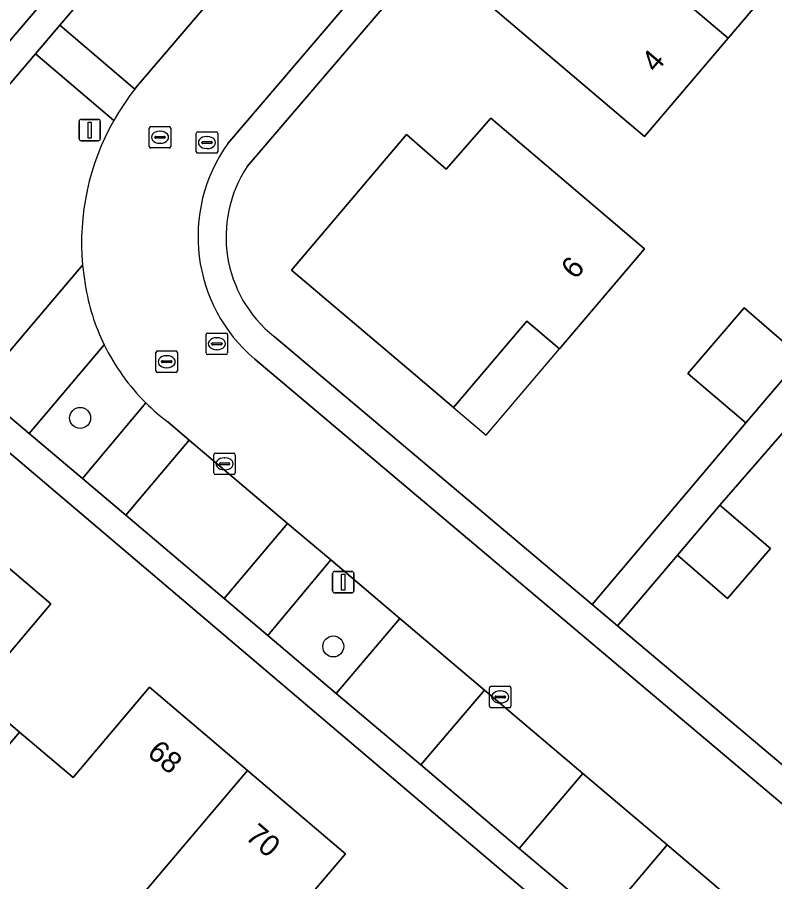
# Model space of a CAD drawing. Extents: x 156412 to 157779, y 382335 to 383768.
# Drawn here: x 156801.54 to 156836.83, y 382429.31 to 382469.61 of the extents above; entities that cross this region are included whole.
import ezdxf

# ---------------------------------------------------------------- set-up
doc = ezdxf.new("R2010")
doc.units = 0
for name, color, linetype in [('IMGEO_Berm_groen', 7, 'Continuous'), ('IMGEO_Boom', 7, 'Continuous'), ('IMGEO_Erf', 7, 'Continuous'), ('IMGEO_Groenvoorziening', 7, 'Continuous'), ('IMGEO_Kolk', 7, 'Continuous'), ('IMGEO_Lichtmast', 7, 'Continuous'), ('IMGEO_Pand', 7, 'Continuous'), ('IMGEO_Pand_nummerreeks', 7, 'Continuous'), ('IMGEO_Pand_overbouw', 7, 'Continuous'), ('IMGEO_Parkeervlak_open', 7, 'Continuous'), ('IMGEO_Rijbaan_lokaal_open', 7, 'Continuous'), ('IMGEO_Rioolput', 7, 'Continuous'), ('IMGEO_Voetpad_open', 7, 'Continuous')]:
    doc.layers.add(name, color=color, linetype=linetype)

msp = doc.modelspace()

# ---------------------------------------------------------------- linework, layer by layer
at = {"layer": 'IMGEO_Berm_groen'}
for points in [[(156806.038, 382464.795), (156802.386, 382467.905), (156794.793, 382458.992)], [(156795.115, 382456.117), (156799.666, 382452.263), (156804.586, 382458.056)], [(156805.592, 382454.345), (156802.099, 382450.202), (156804.578, 382448.103), (156807.536, 382451.631)]]:
    msp.add_lwpolyline(points, dxfattribs=at)
for points in [[(156819.362, 382441.59), (156816.15, 382444.311), (156813.213, 382440.791), (156816.404, 382438.089)], [(156835.024, 382428.321), (156831.828, 382431.028), (156828.869, 382427.532), (156832.065, 382424.824)]]:
    msp.add_lwpolyline(points, close=True, dxfattribs=at)
for centre, radius, start, end in [((156816.088, 382459.104), 11.549, 150.4766, 185.205), ((156814.578, 382458.729), 9.998, 206.0032, 225.2238)]:
    msp.add_arc(centre, radius, start, end, dxfattribs=at)
at = {"layer": 'IMGEO_Boom'}
for centre in [(156804.472, 382450.932), (156816.266, 382440.281)]:
    msp.add_circle(centre, 0.489, dxfattribs=at)
at = {"layer": 'IMGEO_Erf'}
for points in [[(156877.342, 382453.394), (156835.001, 382489.257), (156812.259, 382462.651)], [(156813.512, 382454.727), (156828.335, 382442.229), (156835.48, 382450.702), (156832.784, 382453.003), (156835.405, 382456.06), (156838.087, 382453.751), (156844.039, 382460.712), (156843.159, 382461.477), (156846.108, 382464.976), (156848.523, 382462.877), (156845.52, 382459.424), (156844.272, 382457.989), (156844.07, 382458.164), (156843.904, 382457.972), (156840.037, 382453.506), (156842.315, 382451.578), (156839.698, 382448.487), (156837.386, 382450.444), (156834.276, 382446.87), (156836.632, 382444.85), (156834.638, 382442.513), (156832.298, 382444.54), (156829.512, 382441.236), (156849.402, 382424.466)], [(156849.783, 382408.111), (156821.763, 382431.828), (156791.675, 382457.364), (156791.237, 382457.729), (156772.208, 382435.618), (156781.23, 382428.836)], [(156799.87, 382429.132), (156797.367, 382431.255), (156798.968, 382433.123), (156796.887, 382434.907), (156796.85, 382434.939), (156796.239, 382434.225), (156791.957, 382437.897), (156790.909, 382436.674), (156790.691, 382436.861), (156788.408, 382438.819), (156783.803, 382442.767), (156791.692, 382451.968), (156796.235, 382448.073), (156792.687, 382443.876), (156794.997, 382441.95), (156798.545, 382446.146), (156803.106, 382442.264), (156799.551, 382438.056), (156801.645, 382436.286), (156804.14, 382434.178), (156807.696, 382438.387), (156812.265, 382434.503), (156816.834, 382430.618), (156813.267, 382426.411)]]:
    msp.add_lwpolyline(points, dxfattribs=at)
for points in [[(156838.619, 382472.532), (156838.242, 382472.852), (156834.658, 382468.629), (156830.77, 382464.048), (156829.953, 382464.737), (156822.38, 382471.184), (156826.257, 382475.755), (156830.134, 382480.326), (156833.182, 382477.737), (156835.544, 382480.522), (156840.033, 382476.745), (156840.46, 382476.386), (156840.305, 382476.203), (156841.136, 382475.498)], [(156826.802, 382454.147), (156825.278, 382455.442), (156821.862, 382451.425), (156819.783, 382453.194), (156814.326, 382457.818), (156819.671, 382464.14), (156821.52, 382462.535), (156823.603, 382464.901), (156830.766, 382458.81)]]:
    msp.add_lwpolyline(points, close=True, dxfattribs=at)
msp.add_arc((156817.203, 382459.372), 5.933, 146.4463, 231.525, dxfattribs=at)
at = {"layer": 'IMGEO_Groenvoorziening'}
msp.add_lwpolyline([(156759.817, 382444.931), (156760.299, 382444.569), (156772.208, 382435.618), (156791.237, 382457.729), (156791.675, 382457.364), (156810.572, 382479.519), (156831.533, 382504.167), (156830.605, 382504.95), (156826.003, 382508.837)], dxfattribs=at)
at = {"layer": 'IMGEO_Kolk'}
for p, q in [((156810.699, 382448.366), (156810.699, 382449.218)), ((156810.774, 382449.292), (156811.626, 382449.292)), ((156811.7, 382449.218), (156811.7, 382448.366)), ((156810.958, 382448.786), (156810.958, 382448.798)), ((156811.396, 382448.749), (156810.998, 382448.749)), ((156811.001, 382448.835), (156811.399, 382448.835)), ((156811.187, 382449.072), (156811.212, 382449.072)), ((156811.442, 382448.798), (156811.442, 382448.786)), ((156811.626, 382448.292), (156810.774, 382448.292)), ((156811.21, 382448.512), (156811.185, 382448.512)), ((156823.543, 382437.499), (156823.543, 382438.351)), ((156823.618, 382438.425), (156824.47, 382438.425)), ((156824.544, 382438.351), (156824.544, 382437.499)), ((156823.802, 382437.919), (156823.802, 382437.931)), ((156824.24, 382437.882), (156823.842, 382437.882)), ((156823.845, 382437.968), (156824.243, 382437.968)), ((156824.031, 382438.205), (156824.056, 382438.205)), ((156824.286, 382437.931), (156824.286, 382437.919)), ((156824.47, 382437.425), (156823.618, 382437.425)), ((156824.054, 382437.645), (156824.029, 382437.645))]:
    msp.add_line(p, q, dxfattribs=at)
for points in [[(156810.699, 382448.366), (156810.699, 382449.218)], [(156810.774, 382449.292), (156811.626, 382449.292)], [(156811.7, 382449.218), (156811.7, 382448.366)], [(156811.626, 382448.292), (156810.774, 382448.292)], [(156823.543, 382437.499), (156823.543, 382438.351)], [(156823.618, 382438.425), (156824.47, 382438.425)], [(156824.544, 382438.351), (156824.544, 382437.499)], [(156824.47, 382437.425), (156823.618, 382437.425)]]:
    msp.add_lwpolyline(points, dxfattribs=at)
for centre, radius, start, end in [((156810.776, 382449.216), 0.0765, 91.552, 178.448), ((156810.776, 382449.216), 0.0765, 91.552, 178.448), ((156811.624, 382449.216), 0.0765, 1.552, 88.448), ((156811.624, 382449.216), 0.0765, 1.552, 88.448), ((156810.998, 382448.795), 0.0403, 85.8775, 175.7526), ((156810.995, 382448.785), 0.0366, 178.938, 274.7102), ((156811.399, 382448.792), 0.043, 264.8664, 352.4533), ((156811.403, 382448.797), 0.0386, 1.7309, 96.639), ((156810.776, 382448.368), 0.0765, 181.552, 268.448), ((156810.776, 382448.368), 0.0765, 181.552, 268.448), ((156811.624, 382448.368), 0.0765, 271.552, 358.448), ((156811.624, 382448.368), 0.0765, 271.552, 358.448), ((156823.62, 382438.349), 0.0765, 91.552, 178.448), ((156823.62, 382438.349), 0.0765, 91.552, 178.448), ((156824.468, 382438.349), 0.0765, 1.552, 88.448), ((156824.468, 382438.349), 0.0765, 1.552, 88.448), ((156823.842, 382437.928), 0.0403, 85.8775, 175.7526), ((156823.839, 382437.918), 0.0366, 178.938, 274.7102), ((156824.243, 382437.925), 0.043, 264.8664, 352.4533), ((156824.247, 382437.93), 0.0386, 1.7309, 96.639), ((156823.62, 382437.501), 0.0765, 181.552, 268.448), ((156823.62, 382437.501), 0.0765, 181.552, 268.448), ((156824.468, 382437.501), 0.0765, 271.552, 358.448), ((156824.468, 382437.501), 0.0765, 271.552, 358.448)]:
    msp.add_arc(centre, radius, start, end, dxfattribs=at)
for centre, major_axis, ratio, start_param, end_param in [((156811.186, 382448.792), (-0.387, 0.002), 0.722429, 4.712389, 7.853982), ((156811.211, 382448.792), (-0.39, 0.002), 0.717154, 1.570796, 4.712389), ((156824.03, 382437.925), (-0.387, 0.002), 0.722429, 4.712389, 7.853982), ((156824.055, 382437.925), (-0.39, 0.002), 0.717154, 1.570796, 4.712389)]:
    msp.add_ellipse(centre, major_axis=major_axis, ratio=ratio, start_param=start_param, end_param=end_param, dxfattribs=at)
at = {"layer": 'IMGEO_Lichtmast'}
for p, q in [((156804.521, 382464.85), (156805.311, 382464.85)), ((156805.311, 382464.85), (156804.521, 382464.85)), ((156804.421, 382463.95), (156804.421, 382464.75)), ((156804.421, 382464.75), (156804.421, 382463.95)), ((156805.411, 382464.75), (156805.411, 382463.95)), ((156805.411, 382463.95), (156805.411, 382464.75)), ((156805.311, 382463.85), (156804.521, 382463.85)), ((156804.521, 382463.85), (156805.311, 382463.85)), ((156816.234, 382442.874), (156816.234, 382443.674)), ((156816.234, 382443.674), (156816.234, 382442.874)), ((156816.334, 382443.774), (156817.124, 382443.774)), ((156817.124, 382443.774), (156816.334, 382443.774)), ((156817.224, 382443.674), (156817.224, 382442.874)), ((156817.224, 382442.874), (156817.224, 382443.674)), ((156817.124, 382442.774), (156816.334, 382442.774)), ((156816.334, 382442.774), (156817.124, 382442.774))]:
    msp.add_line(p, q, dxfattribs=at)
for points in [[(156804.841, 382464.725), (156804.991, 382464.725), (156804.991, 382463.975), (156804.841, 382463.975), (156804.841, 382464.725)], [(156816.654, 382443.649), (156816.804, 382443.649), (156816.804, 382442.899), (156816.654, 382442.899), (156816.654, 382443.649)]]:
    msp.add_lwpolyline(points, dxfattribs=at)
for centre, start, end in [((156804.521, 382464.75), 90, 180), ((156804.521, 382464.75), 90, 180), ((156805.311, 382464.75), 0, 90), ((156805.311, 382464.75), 360, 90), ((156804.521, 382463.95), 180, 270), ((156804.521, 382463.95), 180, 270), ((156805.311, 382463.95), 270, 0), ((156805.311, 382463.95), 270, 0), ((156816.334, 382443.674), 90, 180), ((156816.334, 382443.674), 90, 180), ((156817.124, 382443.674), 0, 90), ((156817.124, 382443.674), 360, 90), ((156816.334, 382442.874), 180, 270), ((156816.334, 382442.874), 180, 270), ((156817.124, 382442.874), 270, 0), ((156817.124, 382442.874), 270, 0)]:
    msp.add_arc(centre, 0.1, start, end, dxfattribs=at)
at = {"layer": 'IMGEO_Pand'}
for points in [[(156840.305, 382476.203), (156840.46, 382476.386), (156840.033, 382476.745), (156835.544, 382480.522), (156833.182, 382477.737), (156830.134, 382480.326), (156826.257, 382475.755), (156834.658, 382468.629), (156838.242, 382472.852), (156838.619, 382472.532), (156841.136, 382475.498)], [(156826.257, 382475.755), (156822.38, 382471.184), (156829.953, 382464.737), (156830.77, 382464.048), (156834.658, 382468.629)], [(156823.603, 382464.901), (156821.52, 382462.535), (156819.671, 382464.14), (156814.326, 382457.818), (156819.783, 382453.194), (156821.862, 382451.425), (156825.278, 382455.442), (156826.802, 382454.147), (156830.766, 382458.81)], [(156835.405, 382456.06), (156832.784, 382453.003), (156835.48, 382450.702), (156838.087, 382453.751)], [(156836.632, 382444.85), (156834.276, 382446.87), (156832.298, 382444.54), (156834.638, 382442.513)], [(156803.106, 382442.264), (156798.545, 382446.146), (156794.997, 382441.95), (156791.731, 382438.091), (156791.957, 382437.897), (156796.239, 382434.225), (156796.85, 382434.939), (156796.887, 382434.907), (156798.968, 382433.123), (156801.645, 382436.286), (156799.551, 382438.056)], [(156812.265, 382434.503), (156807.696, 382438.387), (156804.14, 382434.178), (156801.645, 382436.286), (156798.968, 382433.123), (156797.367, 382431.255), (156799.87, 382429.132), (156804.439, 382425.255)], [(156816.834, 382430.618), (156812.265, 382434.503), (156804.439, 382425.255), (156809.01, 382421.376), (156811.294, 382419.439), (156815.548, 382424.466), (156813.267, 382426.411)]]:
    msp.add_lwpolyline(points, close=True, dxfattribs=at)
at = {"layer": 'IMGEO_Pand_overbouw'}
msp.add_lwpolyline([(156821.862, 382451.425), (156823.386, 382450.129), (156826.802, 382454.147), (156825.278, 382455.442)], close=True, dxfattribs=at)
at = {"layer": 'IMGEO_Parkeervlak_open'}
for points in [[(156811.969, 382472.085), (156808.479, 382475.058), (156803.522, 382469.239), (156807.022, 382466.261), (156807.102, 382466.361)], [(156816.15, 382444.311), (156814.14, 382446.014), (156811.181, 382442.512), (156813.213, 382440.791)], [(156819.362, 382441.59), (156816.404, 382438.089), (156820.341, 382434.755), (156823.304, 382438.249)], [(156827.897, 382434.359), (156824.929, 382430.869), (156828.869, 382427.532), (156831.828, 382431.028)]]:
    msp.add_lwpolyline(points, close=True, dxfattribs=at)
for points in [[(156804.586, 382458.056), (156799.666, 382452.263), (156802.099, 382450.202), (156805.592, 382454.345)], [(156807.536, 382451.631), (156804.578, 382448.103), (156806.596, 382446.395), (156809.556, 382449.899)], [(156809.556, 382449.899), (156808.554, 382450.748)]]:
    msp.add_lwpolyline(points, dxfattribs=at)
for centre, radius, start, end in [((156816.681, 382459.188), 12.148, 185.3484, 189.6499), ((156814.618, 382458.741), 10.04, 189.1059, 205.9667), ((156814.491, 382458.621), 9.86, 225.1438, 232.9803)]:
    msp.add_arc(centre, radius, start, end, dxfattribs=at)
at = {"layer": 'IMGEO_Rijbaan_lokaal_open'}
for points in [[(156832.43, 382495.337), (156831.034, 382493.709), (156830.667, 382494.021), (156829.67, 382492.851), (156828.138, 382491.056), (156821.629, 382483.423), (156818.391, 382479.627), (156815.15, 382475.827), (156813.523, 382473.914), (156811.969, 382472.085), (156807.102, 382466.361), (156807.022, 382466.261)], [(156811.356, 382463.724), (156834.843, 382491.235), (156835.788, 382492.342)], [(156848.473, 382423.417), (156812.607, 382453.674)], [(156808.554, 382450.748), (156809.556, 382449.899), (156814.14, 382446.014), (156816.15, 382444.311), (156819.362, 382441.59), (156823.304, 382438.249), (156827.897, 382434.359), (156831.828, 382431.028), (156835.024, 382428.321), (156837.066, 382426.591), (156839.363, 382424.645), (156843.196, 382421.398), (156849.115, 382416.384), (156853.042, 382413.045), (156860.624, 382406.633), (156866.4, 382401.754), (156868.942, 382399.606), (156874.7, 382394.741), (156877.228, 382392.605), (156879.193, 382390.945), (156884.481, 382386.477), (156887.238, 382384.148), (156891.089, 382380.895), (156892.165, 382379.985)]]:
    msp.add_lwpolyline(points, dxfattribs=at)
for points in [[(156809.556, 382449.899), (156806.596, 382446.395), (156811.181, 382442.512), (156814.14, 382446.014)], [(156823.304, 382438.249), (156820.341, 382434.755), (156822.632, 382432.815), (156824.929, 382430.869), (156827.897, 382434.359)]]:
    msp.add_lwpolyline(points, close=True, dxfattribs=at)
for centre, radius, start, end in [((156816.128, 382459.086), 11.593, 141.7626, 150.4972), ((156816.088, 382459.104), 11.549, 150.4766, 185.205), ((156817.438, 382459.378), 7.475, 144.4535, 229.7376), ((156816.681, 382459.188), 12.148, 185.3484, 189.6499), ((156814.618, 382458.741), 10.04, 189.1059, 205.9667), ((156814.578, 382458.729), 9.998, 206.0032, 225.2238), ((156814.491, 382458.621), 9.86, 225.1438, 232.9803)]:
    msp.add_arc(centre, radius, start, end, dxfattribs=at)
at = {"layer": 'IMGEO_Rioolput'}
for p, q in [((156807.694, 382463.588), (156807.694, 382464.44)), ((156807.769, 382464.514), (156808.621, 382464.514)), ((156808.695, 382464.44), (156808.695, 382463.588)), ((156807.953, 382464.008), (156807.953, 382464.02)), ((156807.996, 382464.057), (156808.394, 382464.057)), ((156808.182, 382464.294), (156808.207, 382464.294)), ((156808.437, 382464.02), (156808.437, 382464.008)), ((156809.879, 382463.342), (156809.879, 382464.194)), ((156809.954, 382464.268), (156810.806, 382464.268)), ((156810.367, 382464.048), (156810.392, 382464.048)), ((156810.88, 382464.194), (156810.88, 382463.342)), ((156808.391, 382463.971), (156807.993, 382463.971)), ((156808.205, 382463.734), (156808.18, 382463.734)), ((156810.138, 382463.762), (156810.138, 382463.774)), ((156810.576, 382463.725), (156810.178, 382463.725)), ((156810.181, 382463.811), (156810.579, 382463.811)), ((156810.622, 382463.774), (156810.622, 382463.762)), ((156808.621, 382463.514), (156807.769, 382463.514)), ((156810.806, 382463.268), (156809.954, 382463.268)), ((156810.39, 382463.488), (156810.365, 382463.488)), ((156810.34, 382453.962), (156810.34, 382454.814)), ((156810.415, 382454.888), (156811.267, 382454.888)), ((156811.341, 382454.814), (156811.341, 382453.962)), ((156810.599, 382454.382), (156810.599, 382454.394)), ((156811.037, 382454.345), (156810.639, 382454.345)), ((156810.642, 382454.431), (156811.04, 382454.431)), ((156810.828, 382454.668), (156810.853, 382454.668)), ((156811.083, 382454.394), (156811.083, 382454.382)), ((156808.003, 382453.126), (156808.003, 382453.978)), ((156808.078, 382454.052), (156808.93, 382454.052)), ((156809.004, 382453.978), (156809.004, 382453.126)), ((156810.851, 382454.108), (156810.826, 382454.108)), ((156808.262, 382453.546), (156808.262, 382453.558)), ((156808.305, 382453.595), (156808.703, 382453.595)), ((156808.491, 382453.832), (156808.516, 382453.832)), ((156808.746, 382453.558), (156808.746, 382453.546)), ((156811.267, 382453.888), (156810.415, 382453.888)), ((156808.7, 382453.509), (156808.302, 382453.509)), ((156808.514, 382453.272), (156808.489, 382453.272)), ((156808.93, 382453.052), (156808.078, 382453.052))]:
    msp.add_line(p, q, dxfattribs=at)
for points in [[(156807.694, 382463.588), (156807.694, 382464.44)], [(156807.769, 382464.514), (156808.621, 382464.514)], [(156808.695, 382464.44), (156808.695, 382463.588)], [(156809.879, 382463.342), (156809.879, 382464.194)], [(156809.954, 382464.268), (156810.806, 382464.268)], [(156810.88, 382464.194), (156810.88, 382463.342)], [(156808.621, 382463.514), (156807.769, 382463.514)], [(156810.806, 382463.268), (156809.954, 382463.268)], [(156810.34, 382453.962), (156810.34, 382454.814)], [(156810.415, 382454.888), (156811.267, 382454.888)], [(156811.341, 382454.814), (156811.341, 382453.962)], [(156808.003, 382453.126), (156808.003, 382453.978)], [(156808.078, 382454.052), (156808.93, 382454.052)], [(156809.004, 382453.978), (156809.004, 382453.126)], [(156811.267, 382453.888), (156810.415, 382453.888)], [(156808.93, 382453.052), (156808.078, 382453.052)]]:
    msp.add_lwpolyline(points, dxfattribs=at)
for centre, radius, start, end in [((156807.771, 382464.438), 0.0765, 91.552, 178.448), ((156807.771, 382464.438), 0.0765, 91.552, 178.448), ((156808.619, 382464.438), 0.0765, 1.552, 88.448), ((156808.619, 382464.438), 0.0765, 1.552, 88.448), ((156807.993, 382464.017), 0.0403, 85.8775, 175.7526), ((156807.99, 382464.007), 0.0366, 178.938, 274.7102), ((156808.394, 382464.014), 0.043, 264.8664, 352.4533), ((156808.398, 382464.019), 0.0386, 1.7309, 96.639), ((156809.956, 382464.192), 0.0765, 91.552, 178.448), ((156809.956, 382464.192), 0.0765, 91.552, 178.448), ((156810.804, 382464.192), 0.0765, 1.552, 88.448), ((156810.804, 382464.192), 0.0765, 1.552, 88.448), ((156810.178, 382463.771), 0.0403, 85.8775, 175.7526), ((156810.175, 382463.761), 0.0366, 178.938, 274.7102), ((156810.579, 382463.768), 0.043, 264.8664, 352.4533), ((156810.583, 382463.773), 0.0386, 1.7309, 96.639), ((156807.771, 382463.59), 0.0765, 181.552, 268.448), ((156807.771, 382463.59), 0.0765, 181.552, 268.448), ((156808.619, 382463.59), 0.0765, 271.552, 358.448), ((156808.619, 382463.59), 0.0765, 271.552, 358.448), ((156809.956, 382463.344), 0.0765, 181.552, 268.448), ((156809.956, 382463.344), 0.0765, 181.552, 268.448), ((156810.804, 382463.344), 0.0765, 271.552, 358.448), ((156810.804, 382463.344), 0.0765, 271.552, 358.448), ((156810.417, 382454.812), 0.0765, 91.552, 178.448), ((156810.417, 382454.812), 0.0765, 91.552, 178.448), ((156811.265, 382454.812), 0.0765, 1.552, 88.448), ((156811.265, 382454.812), 0.0765, 1.552, 88.448), ((156810.639, 382454.391), 0.0403, 85.8775, 175.7526), ((156810.636, 382454.381), 0.0366, 178.938, 274.7102), ((156811.04, 382454.388), 0.043, 264.8664, 352.4533), ((156811.044, 382454.393), 0.0386, 1.7309, 96.639), ((156808.08, 382453.976), 0.0765, 91.552, 178.448), ((156808.08, 382453.976), 0.0765, 91.552, 178.448), ((156808.928, 382453.976), 0.0765, 1.552, 88.448), ((156808.928, 382453.976), 0.0765, 1.552, 88.448), ((156810.417, 382453.964), 0.0765, 181.552, 268.448), ((156810.417, 382453.964), 0.0765, 181.552, 268.448), ((156811.265, 382453.964), 0.0765, 271.552, 358.448), ((156811.265, 382453.964), 0.0765, 271.552, 358.448), ((156808.302, 382453.555), 0.0403, 85.8775, 175.7526), ((156808.299, 382453.545), 0.0366, 178.938, 274.7102), ((156808.703, 382453.552), 0.043, 264.8664, 352.4533), ((156808.707, 382453.557), 0.0386, 1.7309, 96.639), ((156808.08, 382453.128), 0.0765, 181.552, 268.448), ((156808.08, 382453.128), 0.0765, 181.552, 268.448), ((156808.928, 382453.128), 0.0765, 271.552, 358.448), ((156808.928, 382453.128), 0.0765, 271.552, 358.448)]:
    msp.add_arc(centre, radius, start, end, dxfattribs=at)
for centre, major_axis, ratio, start_param, end_param in [((156808.181, 382464.014), (-0.387, 0.002), 0.722429, 4.712389, 7.853982), ((156808.206, 382464.014), (-0.39, 0.002), 0.717154, 1.570796, 4.712389), ((156810.366, 382463.768), (-0.387, 0.002), 0.722429, 4.712389, 7.853982), ((156810.391, 382463.768), (-0.39, 0.002), 0.717154, 1.570796, 4.712389), ((156810.827, 382454.388), (-0.387, 0.002), 0.722429, 4.712389, 7.853982), ((156810.852, 382454.388), (-0.39, 0.002), 0.717154, 1.570796, 4.712389), ((156808.49, 382453.552), (-0.387, 0.002), 0.722429, 4.712389, 7.853982), ((156808.515, 382453.552), (-0.39, 0.002), 0.717154, 1.570796, 4.712389)]:
    msp.add_ellipse(centre, major_axis=major_axis, ratio=ratio, start_param=start_param, end_param=end_param, dxfattribs=at)
at = {"layer": 'IMGEO_Voetpad_open'}
for points in [[(156794.793, 382458.992), (156802.386, 382467.905), (156803.522, 382469.239), (156808.479, 382475.058), (156810.033, 382476.883), (156811.563, 382478.679), (156814.902, 382482.597), (156818.136, 382486.392), (156824.64, 382494.023), (156826.198, 382495.85), (156827.163, 382496.983), (156832.477, 382503.264), (156832.153, 382503.644), (156831.533, 382504.167), (156810.572, 382479.519), (156791.675, 382457.364), (156821.763, 382431.828), (156849.783, 382408.111), (156876.247, 382385.72), (156880.938, 382381.751), (156899.797, 382365.794), (156922.237, 382392.249)], [(156835.001, 382489.257), (156834.843, 382491.235), (156811.356, 382463.724)], [(156812.259, 382462.651), (156835.001, 382489.257)], [(156803.522, 382469.239), (156802.386, 382467.905), (156806.038, 382464.795)], [(156807.022, 382466.261), (156803.522, 382469.239)], [(156828.869, 382427.532), (156824.929, 382430.869), (156822.632, 382432.815), (156820.341, 382434.755), (156816.404, 382438.089), (156813.213, 382440.791), (156811.181, 382442.512), (156806.596, 382446.395), (156804.578, 382448.103), (156802.099, 382450.202), (156799.666, 382452.263), (156795.115, 382456.117)], [(156849.402, 382424.466), (156829.512, 382441.236), (156828.335, 382442.229), (156813.512, 382454.727)], [(156812.607, 382453.674), (156848.473, 382423.417)]]:
    msp.add_lwpolyline(points, dxfattribs=at)
msp.add_lwpolyline([(156845.52, 382459.424), (156844.039, 382460.712), (156838.087, 382453.751), (156835.48, 382450.702), (156828.335, 382442.229), (156829.512, 382441.236), (156832.298, 382444.54), (156834.276, 382446.87), (156837.386, 382450.444), (156840.037, 382453.506), (156843.904, 382457.972), (156844.07, 382458.164), (156844.272, 382457.989)], close=True, dxfattribs=at)
for centre, radius, start, end in [((156816.128, 382459.086), 11.593, 141.7626, 150.4972), ((156817.438, 382459.378), 7.475, 144.4535, 229.7376), ((156817.203, 382459.372), 5.933, 146.4463, 231.525)]:
    msp.add_arc(centre, radius, start, end, dxfattribs=at)

# ---------------------------------------------------------------- texts
at = {"layer": 'IMGEO_Pand_nummerreeks'}
for s, rotation, p in [('4', 49.4806, (156831.29, 382466.981)), ('6', 49.4348, (156827.548, 382457.343)), ('68', 319.6351, (156807.543, 382435.235)), ('70', 319.6351, (156812.117, 382431.347))]:
    msp.add_text(s, height=1, rotation=rotation, dxfattribs=at).set_placement(p)

doc.saveas('drawing.dxf')
